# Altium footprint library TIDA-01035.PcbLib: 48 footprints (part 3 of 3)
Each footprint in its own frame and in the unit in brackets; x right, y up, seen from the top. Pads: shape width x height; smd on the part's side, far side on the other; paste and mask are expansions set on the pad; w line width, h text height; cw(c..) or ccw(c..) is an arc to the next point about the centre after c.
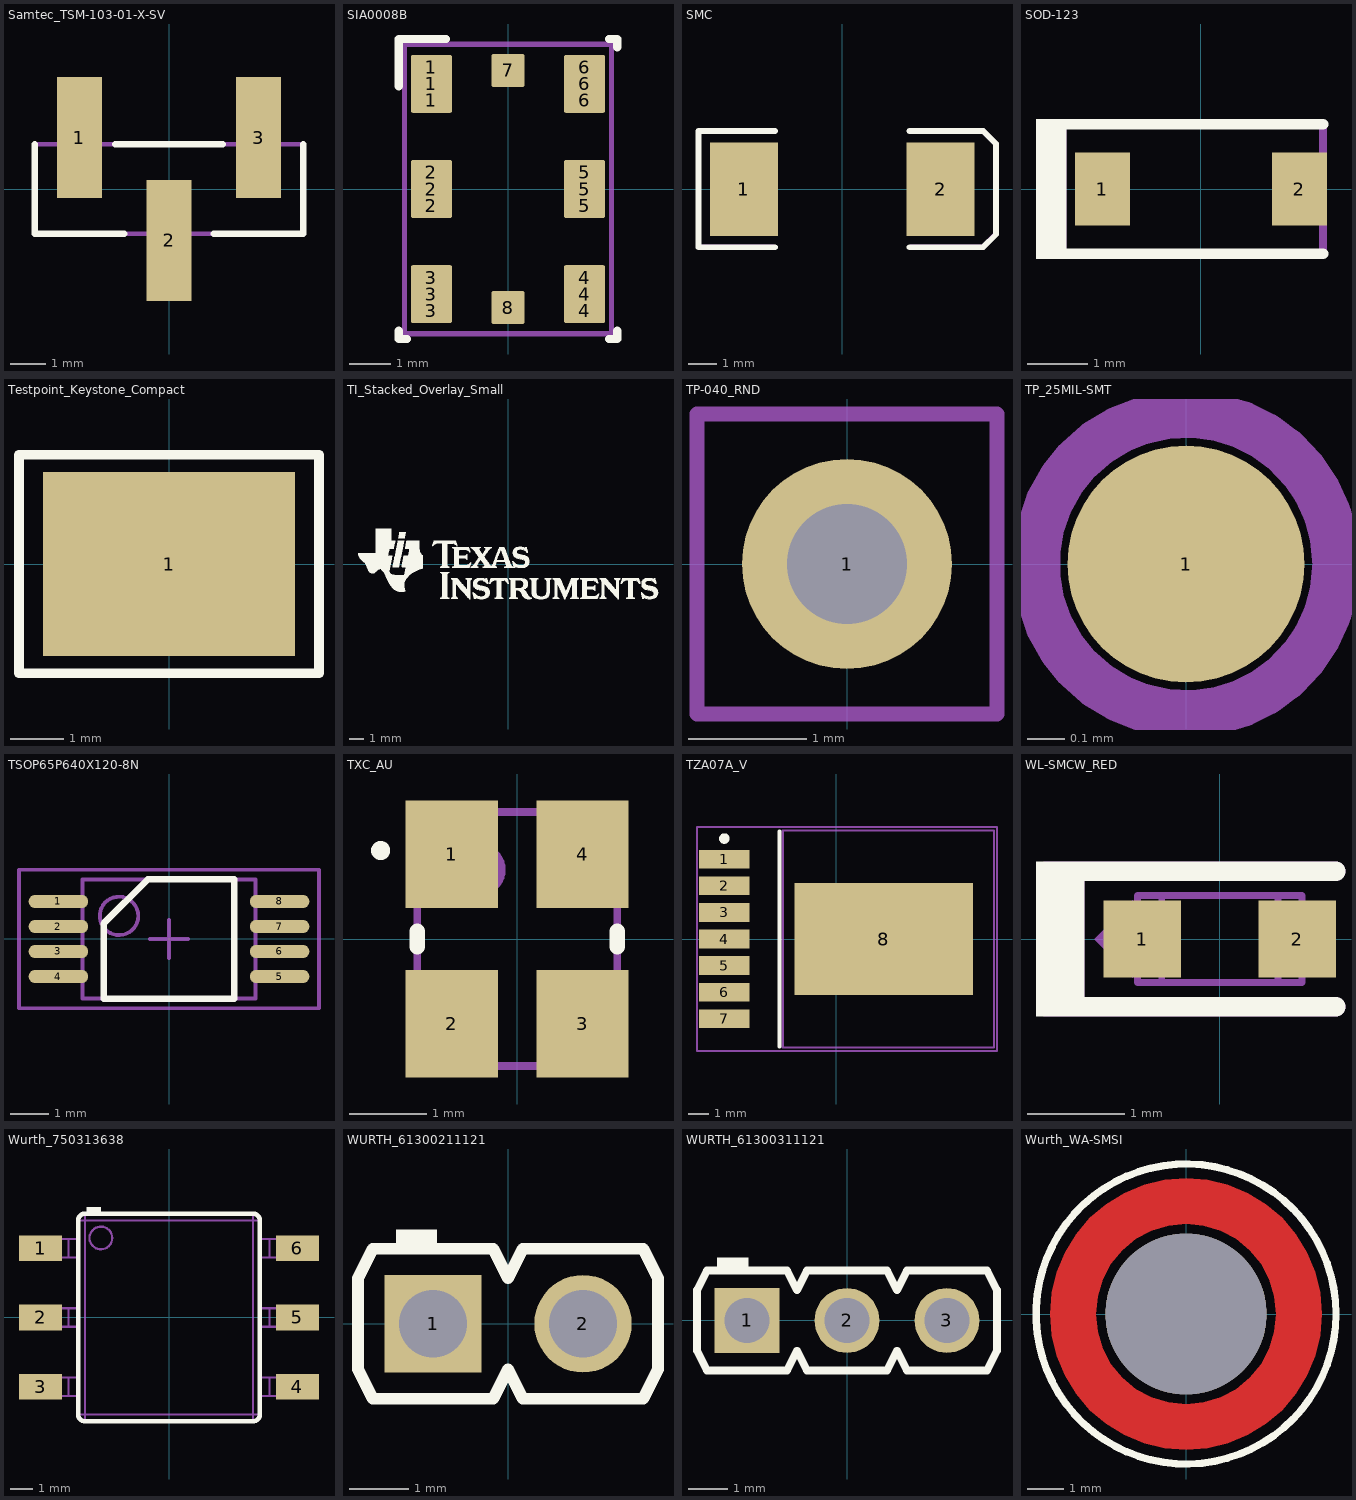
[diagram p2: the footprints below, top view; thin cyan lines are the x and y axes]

## Samtec_TSM-103-01-X-SV [mil] "Samtec recommended land pattern"
height 380
pads (3):
  rect 50x135 smd: 1(-100,57.5) 2(0,-57.5) 3(100,57.5)
Top Overlay:
  lines w7: -150,50 -150,-50 -50,-50 ; -60,50 60,50 ; 50,-50 150,-50 150,50
Mechanical 5:
  lines w5: -112.5,50 -112.5,92 ; -87.5,50 -87.5,92 ; -12.5,-50 -12.5,-92 ; 12.5,-50 12.5,-92 ; 87.5,50 87.5,92 ; 112.5,50 112.5,92 ; -112.5,92 -105.57,104 -94.43,104 -87.5,92 ; -112.5,92 -87.5,92 ; -12.5,-92 -5.57,-104 5.57,-104 12.5,-92 ; -12.5,-92 12.5,-92 ; 87.5,92 94.43,104 105.57,104 112.5,92 ; 87.5,92 112.5,92 ; -150,-50 -150,50 150,50 150,-50 -150,-50
  text ".Designator" at -110,-30 h60
3D body: height 380.6, standoff 0.6, extent -149.99,-104.01 150.01,103.99

## SIA0008B [mm] "SIP 8-Leads, Body 5x7mm"
height 1.1
pads (20):
  rrect50% 1x0.6 on Top Paste: 1(-1.85,2.14) 1(-1.85,2.94) 2(-1.85,-0.4) 2(-1.85,0.4) 3(-1.85,-2.94) 3(-1.85,-2.14) 4(1.85,-2.94) 4(1.85,-2.14) 5(1.85,-0.4) 5(1.85,0.4) 6(1.85,2.14) 6(1.85,2.94)
  rrect10% 1x1.4 smd paste-0.5: 1(-1.85,2.54) 2(-1.85,0) 3(-1.85,-2.54) 4(1.85,-2.54) 5(1.85,0) 6(1.85,2.54)
  rrect12% 0.8x0.8 smd: 7(0,2.865) 8(0,-2.865)
Top Overlay:
  lines w0.2: -2.64,-3.425 -2.64,-3.625 -2.44,-3.625 ; -2.64,2.485 -2.64,3.625 -1.5,3.625 ; 2.44,-3.625 2.64,-3.625 2.64,-3.425 ; 2.44,3.625 2.64,3.625 2.64,3.425
Mechanical 5:
  circle w0.1: c-1.84,2.54 r0.25
  lines w0.127: -2.5,-3.5 -2.5,3.5 2.5,3.5 2.5,-3.5 -2.5,-3.5
  text ".Designator" at -1.4,0 h0.76
3D body: height 1.1, standoff 0, extent -2.564,-3.564 2.564,3.564
3D body: height 1.13, standoff 0, extent -2.162,2.218 -1.518,2.862

## SMC [mm] "DO-214-AB/SMC; 2 C-Bend Leads; Body 7.9 x 5.9 mm, inc. leads (LxW)"
height 2.65
pads (2):
  rect 2.4x3.3 smd: 1(-3.475,0) 2(3.475,0)
Top Overlay:
  lines w0.2: -2.375,-2.05 -5.075,-2.05 -5.075,2.05 -2.375,2.05 ; 2.375,-2.05 4.975,-2.05 5.425,-1.6 5.425,1.6 4.975,2.055 ; 2.375,2.05 4.975,2.05
Mechanical 5:
  lines w0.152: -2.413,-2.032 -5.08,-2.032 -5.08,2.032 -2.413,2.032 ; 2.413,-2.032 4.953,-2.032 5.461,-1.524 5.461,1.524 4.953,2.032 2.413,2.032
  text ".designator" at 0,0 h0.64

## SOD-123 [mm] "On Semi recommended land pattern"
height 1.35
pads (2):
  rect 0.915x1.22 smd: 1(-1.637,0) 2(1.637,0)
Top Overlay:
  rectangle: -2.743,-1.168 -2.235,1.168
  lines w0.178: -2.413,-1.079 2.032,-1.079 ; -2.413,1.079 2.032,1.079
Mechanical 5:
  rectangle: -2.743,-1.168 -2.235,1.168
  lines w0.127: -2.413,-1.079 2.032,-1.079 2.032,1.079 -2.413,1.079
  text ".Designator" at -1.956,-0.33 h0.76
3D body: height 1.35, standoff 0, extent -1.932,-0.9 1.932,0.9

## Testpoint_Keystone_Compact [mil] "Compact SMT test point"
height 90.55
pads (1):
  rect 185x135 smd: 1(0,0)
Top Overlay:
  lines w7: -110,-80 -110,-70 -110,70 -110,80 -100,80 -30,80 110,80 110,-80 -100,-80 -110,-80
Mechanical 5:
  lines w5: -65.33,-22.51 -63.43,-23.14 ; -63.92,21.31 -54.27,57.33 63.59,25.75 ; -63.09,21.31 -74.92,21.31 -74.92,-18.69 -75,-20 -74.85,-20.08 -63.43,-23.14 ; 63.25,-18.69 75.08,-18.69 75.08,21.31 75.16,22.61 75.01,22.69 63.59,25.75 ; 64.08,-18.69 54.43,-54.72 -63.43,-23.14 ; 65.49,25.13 63.59,25.75
  text ".Designator" at -55,-5 h30
3D body: height 90.6, standoff 0.6, extent -75.08,-56.03 75.08,56.03

## TI_Stacked_Overlay_Small [mm]
height 0.69
Top Overlay:
  drawing of 18 lines, arcs and shapes, not listed

## TP-040_RND [mil]
height 27.17
pads (1):
  round 70 / inner round 62 / far side round 62 hole 40: 1(0,0)
Mechanical 5:
  lines w5: -50,-50 -50,50 50,50 50,-50 -50,-50

## TP_25MIL-SMT [mm]
height 0.69
pads (1):
  round 0.635 smd mask-0.064: 1(0,0)
Mechanical 5:
  circle w0.127: c0,0 r0.402

## TSOP65P640X120-8N [mm] "TSOP, 8-Leads, Body 3.1x4.5mm (max), Pitch 0.65mm, IPC Medium Density"
height 1.2
pads (8):
  oval 1.55x0.35 smd mask+0.08: 1(-2.875,0.975) 2(-2.875,0.325) 3(-2.875,-0.325) 4(-2.875,-0.975) 5(2.875,-0.975) 6(2.875,-0.325) 7(2.875,0.325) 8(2.875,0.975)
Top Overlay:
  lines w0.17: -1.7,-1.55 -1.7,0.4 -0.55,1.55 1.7,1.55 1.7,-1.55 -1.7,-1.55
Mechanical 5:
  circle w0.1: c-1.3,0.6 r0.5
  lines w0.1: -2.25,-1.55 -2.25,1.55 2.25,1.55 2.25,-1.55 -2.25,-1.55
  text ".Designator" at -1.8,-1.2 h1
Mechanical 15:
  lines w0.1: -0.5,0 0.5,0 ; 0,-0.5 0,0.5 ; -3.9,-1.8 -3.9,1.8 3.9,1.8 3.9,-1.8 -3.9,-1.8
3D body: height 1.2, standoff 0.15, extent -2.25,-1.55 2.25,1.55
3D body: height 1.21, standoff 1, extent -1.809,0.091 -0.791,1.109

## TXC_AU [mm] "SMD, 4-Leads, Body 3.2x2.5mm"
height 1.1
pads (4):
  rect 1.2x1.4 smd: 1(-0.85,1.1) 2(-0.85,-1.1) 3(0.85,-1.1) 4(0.85,1.1)
Top Overlay:
  circle w0.125: c-1.775,1.15 r0.062
  lines w0.2: -1.3,-0.1 -1.3,0.1 ; 1.3,-0.1 1.3,0.1
Mechanical 5:
  circle w0.1: c-0.5,0.9 r0.3
  lines w0.1: -1.3,-1.35 cw(c-1.3,-1.65) -1,-1.65 1,-1.65 cw(c1.3,-1.65) 1.3,-1.35 1.3,1.35 cw(c1.3,1.65) 1,1.65 -1,1.65 cw(c-1.3,1.65) -1.3,1.35 -1.3,-1.35
  text ".Designator" at -0.8,-0.2 h0.45
3D body: height 1.1, standoff 0.8, extent -1.005,-1.355 1.005,1.355
3D body: height 0.8, standoff 0, extent -1.301,-1.651 1.301,1.651
3D body: height 1.11, standoff 0.8, extent -0.805,0.595 -0.195,1.205

## TZA07A_V [mm] "D2-PAK, 8-Leads, Body 9.9x10.2mm, Pitch 1.27mm, Lead Span 13.8mm, NSC Recommended"
height 4.67
pads (8):
  rect 2.41x0.89 smd: 1(-5.35,3.81) 2(-5.35,2.54) 3(-5.35,1.27) 4(-5.35,0) 5(-5.35,-1.27) 6(-5.35,-2.54) 7(-5.35,-3.81)
  rect 8.54x5.35 smd: 8(2.28,0)
Top Overlay:
  circle w0.25: c-5.35,4.805 r0.125
  lines w0.2: -2.7,-5.15 -2.7,5.15
Mechanical 5:
  lines w0.1: -2.55,-5.2 7.55,-5.2 7.55,5.2 -2.55,5.2 -2.55,-5.2
  text ".Designator" at 0.61,0.813 h0.64
Mechanical 15:
  lines w0.1: -0.5,0 0.5,0 ; 0,-0.5 0,0.5 ; -6.655,-5.35 -6.655,5.35 7.7,5.35 7.7,-5.35 -6.655,-5.35
3D body: height 4.67, standoff 0, extent -2.55,-5.2 7.55,5.2

## WL-SMCW_RED [mm] "WURTH"
height 0.8
pads (2):
  rect 0.8x0.8 smd: 1(-0.8,0) 2(0.8,0)
Top Overlay:
  rectangle: -1.9,-0.8 -1.4,0.8
  lines w0.2: -1.6,-0.7 1.2,-0.7 ; -1.6,0.7 1.2,0.7
Mechanical 5:
  region: -0.9,-0.4 -0.9,0.4 -1.3,0
  lines w0.2: -1.65,-0.7 -1.65,0.55 ; 1.2,-0.7 -1.5,-0.7 ; 1.2,0.7 -1.5,0.7 ; -1.5,-0.7 -1.5,0.7 ; -1.5,-0.7 -1.8,-0.7 -1.8,0.7 -1.5,0.7
  text ".Designator" at -0.8,-0.3 h0.45
Mechanical 13:
  lines w0.07: -0.6,-0.45 -0.6,0.45 ; 0.6,-0.45 0.6,0.45 ; -0.85,-0.45 -0.85,0.45 0.85,0.45 0.85,-0.45 -0.85,-0.45
3D body: height 0.35, standoff 0, extent -0.849,-0.449 -0.601,0.449
3D body: height 0.35, standoff 0, extent -0.599,-0.449 0.599,0.449
3D body: height 0.35, standoff 0, extent 0.601,-0.449 0.849,0.449
3D body: height 0.8, standoff 0.35, extent -0.599,-0.449 0.599,0.449

## Wurth_750313638 [mm] "SMD, 6-Leads, Body 8x9.14mm, Pitch 3.05mm"
height 7.62
pads (6):
  rect 1.9x1.14 smd: 1(-5.655,3.05) 2(-5.655,0) 3(-5.655,-3.05) 4(5.655,-3.05) 5(5.655,0) 6(5.655,3.05)
Top Overlay:
  rectangle: -3.625,4.57 -3,4.875
  lines w0.2: -4,-4.27 ccw(c-3.7,-4.27) -3.7,-4.57 3.7,-4.57 ccw(c3.7,-4.27) 4,-4.27 4,4.27 ccw(c3.7,4.27) 3.7,4.57 -3.7,4.57 ccw(c-3.7,4.27) -4,4.27 -4,-4.27
Mechanical 5:
  circle w0.1: c-3,3.5 r0.5
  lines w0.1: -4,-3.455 -4.43,-3.455 ; -4,-2.645 -4.43,-2.645 ; -4,-0.405 -4.43,-0.405 ; -4,0.405 -4.43,0.405 ; -4,2.645 -4.43,2.645 ; -4,3.455 -4.43,3.455 ; 4,-3.455 4.43,-3.455 ; 4,-2.645 4.43,-2.645 ; 4,-0.405 4.43,-0.405 ; 4,0.405 4.43,0.405 ; 4,2.645 4.43,2.645 ; 4,3.455 4.43,3.455 ; -5.47,-3.455 -5.376,-3.455 ; -5.47,-3.455 -6.35,-3.455 -6.35,-2.645 -5.47,-2.645 ; -5.47,-3.455 -5.47,-2.645 ; -5.47,-2.645 -5.376,-2.645 ; -5.47,-0.405 -6.35,-0.405 -6.35,0.405 -5.47,0.405 ; -5.47,-0.405 -5.376,-0.405 ; -5.47,-0.405 -5.47,0.405 ; -5.47,0.405 -5.376,0.405 ; -5.47,2.645 -5.376,2.645 ; -5.47,2.645 -6.35,2.645 -6.35,3.455 -5.47,3.455 ; -5.47,2.645 -5.47,3.455 ; -5.47,3.455 -5.376,3.455 ; -5.376,-3.455 -4.9,-3.455 ; -5.376,-3.455 -5.376,-2.645 ; -5.376,-2.645 -4.9,-2.645 ; -5.376,-0.405 -4.9,-0.405 ; -5.376,-0.405 -5.376,0.405 ; -5.376,0.405 -4.9,0.405 ; -5.376,2.645 -4.9,2.645 ; -5.376,2.645 -5.376,3.455 ; -5.376,3.455 -4.9,3.455 ; -4.9,-3.455 -4.43,-3.455 ; -4.9,-3.455 -4.9,-2.645 ; -4.9,-2.645 -4.43,-2.645 ; -4.9,-0.405 -4.43,-0.405 ; -4.9,-0.405 -4.9,0.405 ; -4.9,0.405 -4.43,0.405 ; -4.9,2.645 -4.43,2.645 ; -4.9,2.645 -4.9,3.455 ; -4.9,3.455 -4.43,3.455 ; -4.43,-3.455 -4.43,-2.645 ; -4.43,-0.405 -4.43,0.405 ; -4.43,2.645 -4.43,3.455 ; -4,-4.27 ccw(c-3.7,-4.27) -3.7,-4.57 ; -4,-4.27 -4,4.27 ; -4,-4.27 -3.7,-4.27 ; -4,4.27 cw(c-3.7,4.27) -3.7,4.57 ; -4,4.27 -3.7,4.27 ; -3.7,-4.57 3.7,-4.57 ; -3.7,-4.57 -3.7,-4.27 ; -3.7,-4.27 -3.7,4.27 ; -3.7,-4.27 3.7,-4.27 ; -3.7,4.27 3.7,4.27 ; -3.7,4.27 -3.7,4.57 ; -3.7,4.57 3.7,4.57 ; 3.7,-4.57 ccw(c3.7,-4.27) 4,-4.27 ; 3.7,-4.57 3.7,-4.27 ; 3.7,-4.27 3.7,4.27 ; 3.7,-4.27 4,-4.27 ; 3.7,4.27 3.7,4.57 ; 3.7,4.27 4,4.27 ; 3.7,4.57 cw(c3.7,4.27) 4,4.27 ; 4,-4.27 4,4.27 ; 4.43,-3.455 4.9,-3.455 ; 4.43,-3.455 4.43,-2.645 ; 4.43,-2.645 4.9,-2.645 ; 4.43,-0.405 4.9,-0.405 ; 4.43,-0.405 4.43,0.405 ; 4.43,0.405 4.9,0.405 ; 4.43,2.645 4.9,2.645 ; 4.43,2.645 4.43,3.455 ; 4.43,3.455 4.9,3.455 ; 4.9,-3.455 5.376,-3.455 ; 4.9,-3.455 4.9,-2.645 ; 4.9,-2.645 5.376,-2.645 ; 4.9,-0.405 5.376,-0.405 ; 4.9,-0.405 4.9,0.405 ; 4.9,0.405 5.376,0.405 ; 4.9,2.645 5.376,2.645 ; 4.9,2.645 4.9,3.455 ; 4.9,3.455 5.376,3.455 ; 5.376,-3.455 5.47,-3.455 ; 5.376,-3.455 5.376,-2.645 ; 5.376,-2.645 5.47,-2.645 ; 5.376,-0.405 5.47,-0.405 ; 5.376,-0.405 5.376,0.405 ; 5.376,0.405 5.47,0.405 ; 5.376,2.645 5.47,2.645 ; 5.376,2.645 5.376,3.455 ; 5.376,3.455 5.47,3.455 ; 5.47,-3.455 6.35,-3.455 6.35,-2.645 5.47,-2.645 ; 5.47,-3.455 5.47,-2.645 ; 5.47,-0.405 6.35,-0.405 6.35,0.405 5.47,0.405 ; 5.47,-0.405 5.47,0.405 ; 5.47,2.645 6.35,2.645 6.35,3.455 5.47,3.455 ; 5.47,2.645 5.47,3.455
  text ".Designator" at -1.524,-0.508 h1.02
3D body: height 7.62, standoff 0, extent -6.35,-4.57 6.35,4.57

## WURTH_61300211121 [mm] "Header, 2.54mm, 2x1, TH"
height 8.89
pads (2):
  rect 1.65x1.65 hole 1.15: 1(-1.27,0)
  round 1.65 hole 1.15: 2(1.27,0)
Top Overlay:
  rectangle: -1.9,1.27 -1.2,1.6
  lines w0.2: -2.54,-0.77 -2.29,-1.27 -0.25,-1.27 0,-0.77 0.25,-1.27 2.29,-1.27 2.54,-0.77 2.54,0.77 2.29,1.27 0.25,1.27 0,0.77 -0.25,1.27 -2.29,1.27 -2.54,0.77 -2.54,-0.77
Mechanical 5:
  lines w0.1: -2.54,-0.77 -2.54,0.77 -2.29,1.27 -0.25,1.27 0,0.77 0.25,1.27 2.29,1.27 2.54,0.77 2.54,-0.77 2.29,-1.27 0.25,-1.27 0,-0.77 -0.25,-1.27 -2.29,-1.27 -2.54,-0.77
  text ".Designator" at -1.524,-0.508 h1.02
3D body: height 8.54, standoff -3, extent -2.54,-1.27 2.54,1.27

## WURTH_61300311121 [mm] "Header, 2.54mm, 3x1, TH"
height 8.89
pads (3):
  rect 1.65x1.65 hole 1.15: 1(-2.54,0)
  round 1.65 hole 1.15: 2(0,0) 3(2.54,0)
Top Overlay:
  rectangle: -3.3,1.3 -2.5,1.6
  lines w0.2: -3.81,-0.77 -3.81,0.77 -3.56,1.27 -1.52,1.27 -1.27,0.77 -1.02,1.27 1.02,1.27 1.27,0.77 1.52,1.27 3.56,1.27 3.81,0.77 3.81,-0.77 3.56,-1.27 1.52,-1.27 1.27,-0.77 1.02,-1.27 -1.02,-1.27 -1.27,-0.77 -1.52,-1.27 -3.56,-1.27 -3.81,-0.77
Mechanical 5:
  lines w0.1: -3.81,-0.77 -3.56,-1.27 -1.52,-1.27 -1.27,-0.77 -1.02,-1.27 1.02,-1.27 1.27,-0.77 1.52,-1.27 3.56,-1.27 3.81,-0.77 3.81,0.77 3.56,1.27 1.52,1.27 1.27,0.77 1.02,1.27 -1.02,1.27 -1.27,0.77 -1.52,1.27 -3.56,1.27 -3.81,0.77 -3.81,-0.77
  text ".Designator" at -1.524,-0.508 h1.02
3D body: height 8.54, standoff -3, extent -3.81,-1.27 3.81,1.27

## Wurth_WA-SMSI [mm] "ROUND STANDOFF M3 STEEL 5MM"
height 5
pads (1):
  round 4.4 hole 4.4 unplated mask+0.254: ""(0,0)
Top Layer:
  region: -3.711,0 -3.666,-0.581 -3.53,-1.147 -3.307,-1.685 -3.003,-2.182 -2.624,-2.624 -2.182,-3.003 -1.685,-3.307 -1.147,-3.53 -0.581,-3.666 0,-3.711 0.581,-3.666 1.147,-3.53 1.685,-3.307 2.182,-3.003 2.624,-2.624 3.003,-2.182 3.307,-1.685 3.53,-1.147 3.666,-0.581 3.711,0 3.7,0 2.466,0 2.418,-0.481 2.278,-0.944 2.05,-1.37 1.744,-1.744 1.37,-2.05 0.944,-2.278 0.481,-2.418 0,-2.466 -0.481,-2.418 -0.944,-2.278 -1.37,-2.05 -1.744,-1.744 -2.05,-1.37 -2.278,-0.944 -2.418,-0.481 -2.466,0 -2.454,0
  region: -3.711,0 -3.666,0.581 -3.53,1.147 -3.307,1.685 -3.003,2.182 -2.624,2.624 -2.182,3.003 -1.685,3.307 -1.147,3.53 -0.581,3.666 0,3.711 0.581,3.666 1.147,3.53 1.685,3.307 2.182,3.003 2.624,2.624 3.003,2.182 3.307,1.685 3.53,1.147 3.666,0.581 3.711,0 3.7,0 2.466,0 2.418,0.481 2.278,0.944 2.05,1.37 1.744,1.744 1.37,2.05 0.944,2.278 0.481,2.418 0,2.466 -0.481,2.418 -0.944,2.278 -1.37,2.05 -1.744,1.744 -2.05,1.37 -2.278,0.944 -2.418,0.481 -2.466,0 -2.454,0
Top Overlay:
  circle w0.2: c0,0 r4.1
Top Paste:
  region: -0.268,-2.184 -0.431,-2.168 -0.846,-2.042 -1.228,-1.838 -1.563,-1.563 -1.838,-1.228 -2.042,-0.846 -2.168,-0.431 -2.184,-0.268 -3.686,-0.268 -3.69,-0.268 -3.666,-0.581 -3.53,-1.147 -3.307,-1.685 -3.003,-2.182 -2.624,-2.624 -2.182,-3.003 -1.685,-3.307 -1.147,-3.53 -0.581,-3.666 -0.27,-3.69 -0.268,-3.67
  region: -2.184,0.268 -2.168,0.431 -2.042,0.846 -1.838,1.228 -1.563,1.563 -1.228,1.838 -0.846,2.042 -0.431,2.168 -0.268,2.184 -0.268,3.686 -0.268,3.69 -0.581,3.666 -1.147,3.53 -1.685,3.307 -2.182,3.003 -2.624,2.624 -3.003,2.182 -3.307,1.685 -3.53,1.147 -3.666,0.581 -3.69,0.27 -3.67,0.268
  region: 2.184,-0.268 2.168,-0.431 2.042,-0.846 1.838,-1.228 1.563,-1.563 1.228,-1.838 0.846,-2.042 0.431,-2.168 0.268,-2.184 0.268,-3.686 0.268,-3.69 0.581,-3.666 1.147,-3.53 1.685,-3.307 2.182,-3.003 2.624,-2.624 3.003,-2.182 3.307,-1.685 3.53,-1.147 3.666,-0.581 3.69,-0.27 3.67,-0.268
  region: 0.268,2.184 0.431,2.168 0.846,2.042 1.228,1.838 1.563,1.563 1.838,1.228 2.042,0.846 2.168,0.431 2.184,0.268 3.686,0.268 3.69,0.268 3.666,0.581 3.53,1.147 3.307,1.685 3.003,2.182 2.624,2.624 2.182,3.003 1.685,3.307 1.147,3.53 0.581,3.666 0.27,3.69 0.268,3.67
Mechanical 5:
  circle w0.1: c0,0 r3
  text ".Designator" at -0.438,-0.156 h0.64
3D body: height 5, standoff -1.4, extent -2.994,-2.976 2.994,3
